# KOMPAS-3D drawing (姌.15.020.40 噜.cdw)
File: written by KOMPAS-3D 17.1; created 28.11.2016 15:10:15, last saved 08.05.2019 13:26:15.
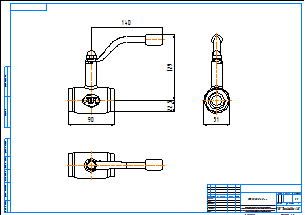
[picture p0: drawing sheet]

Sheet 1: A2, landscape

Title block, sheet 1: name: КШ.15.020.40 рр; material: Внимание! Данный продукт является объектом авторского права ООО «Торговый Дом АДЛ». / Запрещается изменение, копирование, распространение / (в том числе путем копирования на другие сайты и ресурсы в Интернете) / или любое иное использование информации и объектов без предварительного / согласия правообладателя (ООО «Торговый Дом АДЛ»).; sheets: 1; organisation: ООО "Торговый дом АДЛ"; sheet format: A2; stored path: C:\Users\tra\Desktop\2д чертежи\Шаровые краны БИВАЛ\КШ_Бивал_серия_14_15\KOMPAS_2D\КШ.15.020.40 рр.cdw

Views: Вид 1, Проекционный вид 2, Проекционный вид 3
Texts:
  Klimkovich
  ADL
Dimensions and other numbers on the sheet: 90; 140; 129; 22,5; 51; 1:1; 1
